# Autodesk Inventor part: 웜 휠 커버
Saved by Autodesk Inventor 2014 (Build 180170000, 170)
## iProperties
Created: 2026-07
Part Number: 웜 휠 커버
Material: 알루미늄 6061
Document SubType Name: Modeling
Designer: dg
Density: 2.71 g/cm^3
Appearance: 알루미늄 - 평지
Mass: 281.224 g
Surface Area: 333.844 cm^2
Volume: 103.773 cm^3
Author: jhkim
Creation Date: 2026-07-02
Sending System: Autodesk Inventor 2027
Preprocessor: ST-DEVELOPER v20.1
Author: dg
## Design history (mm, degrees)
node "웜 휠 커버1"
node "솔리드1"
node "기준1"
